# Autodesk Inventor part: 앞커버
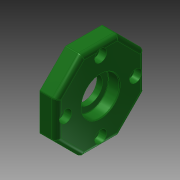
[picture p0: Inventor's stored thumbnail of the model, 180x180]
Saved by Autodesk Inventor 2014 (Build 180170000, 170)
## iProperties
Created: 2015-11
Part Number: 앞커버
Material: 알루미늄 6061
Document SubType Name: Modeling
Designer: mduedu
Density: 1 g/cm^3
Appearance: 매끄러움 - 짙은 산림 녹색
Author: mduedu
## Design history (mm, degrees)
sketch "스케치5" dims "d66" = 58
  geometry: L1 (12.012, 29)-(29, 12.012); L2 (29, 12.012)-(29, -12.012); L3 (29, -12.012)-(12.012, -29); L4 (12.012, -29)-(-12.012, -29); L5 (-12.012, -29)-(-29, -12.012); L6 (-29, -12.012)-(-29, 12.012); L7 (-29, 12.012)-(-12.012, 29); L8 (-12.012, 29)-(12.012, 29); 4 further points
  constraints: 16 end point, 2 coincident, 2 vertical alignment, 1 midpoint, 19 other
extrude "돌출2" new body sketch "스케치5" distance "d67" = 11; taper "d68" = 0 deg
sketch "스케치6"
  geometry: C1 r 16 at (0, 0); 1 further point
  constraints: 1 centre point, 1 coincident
  dimensions: "d69" = 32 diameter of C1
extrude "돌출3" join sketch "스케치6" distance "d70" = 3; taper "d71" = 0 deg
hole "구멍7" diameter "d98" = 28; stored, may be unused: countersink angle "d102" = 90 deg, drill point angle "d104" = 0 deg; dims "d99" = 6, "d100" = 4, "d101" = 2, "d103" = 3, "d145" = 10, "d146" = 10
hole "구멍8" diameter "d107" = 25; stored, may be unused: countersink angle "d111" = 90 deg, drill point angle "d113" = 0 deg; dims "d108" = 6, "d109" = 4, "d110" = 2, "d112" = 7.3, "d143" = 10, "d144" = 10
hole "구멍9" diameter "d116" = 17; stored, may be unused: countersink angle "d120" = 90 deg, drill point angle "d122" = 0 deg; dims "d114" = 10, "d115" = 10, "d117" = 6, "d118" = 4, "d119" = 2, "d121" = 7.7
chamfer "모따기2" distance "d123" = 0.6; stored, may be unused: second distance "d124" = 2, angle "d125" = 30 deg
fillet "모깎기11" dims "d126" = 0.3
fillet "모깎기12" dims "d127" = 1
fillet "모깎기13" dims "d128" = 3
fillet "모깎기14" dims "d129" = 3
fillet "모깎기15" dims "d130" = 0.3
sketch "스케치8" dims "d131" = 46
  geometry: 3 further points
  constraints: 2 vertical alignment, 1 coincident, 2 other
hole "구멍10" sketch "스케치8" at (0, 23) diameter "d132" = 4.5; stored, may be unused: countersink angle "d136" = 90 deg, drill point angle "d138" = 0 deg; dims "d133" = 6, "d134" = 8, "d135" = 4.6, "d137" = 7.7
node "솔리드2"
pattern_circular "원형 패턴4" dims angle "d140" = 360 deg
